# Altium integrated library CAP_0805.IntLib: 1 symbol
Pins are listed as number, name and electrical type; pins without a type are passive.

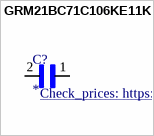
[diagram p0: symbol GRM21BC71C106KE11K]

## GRM21BC71C106KE11K
designator C?
SMD Capacitor X7S(EIA) with Capacitance: 10uF Tol. 10%. Rated Voltage: 16Vdc; MP: GRM21BC71C106KE11K; MF: Murata Electronics
footprint CAPC2012X135N
pins: 1, 2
